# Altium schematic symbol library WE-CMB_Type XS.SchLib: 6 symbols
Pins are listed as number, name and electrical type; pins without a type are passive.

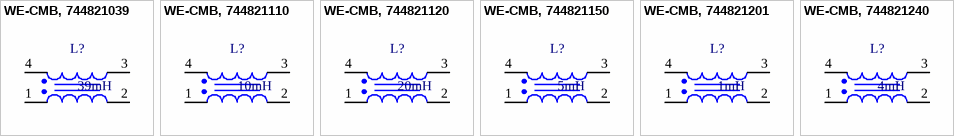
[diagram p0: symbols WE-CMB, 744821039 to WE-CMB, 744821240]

## WE-CMB, 744821039
designator L?, comment 39mH
WE-CMB Common Mode Power Line Choke, Type XS, 39mH; PartNumber: 744821039
footprint WE-CMB_Type XS
pins: 1, 2, 3, 4

## WE-CMB, 744821110
designator L?, comment 10mH
WE-CMB Common Mode Power Line Choke, Type XS, 10mH; PartNumber: 744821110
footprint WE-CMB_Type XS
pins: 1, 2, 3, 4

## WE-CMB, 744821120
designator L?, comment 20mH
WE-CMB Common Mode Power Line Choke, Type XS, 20mH; PartNumber: 744821120
footprint WE-CMB_Type XS_744821120
pins: 1, 2, 3, 4

## WE-CMB, 744821150
designator L?, comment 5mH
WE-CMB Common Mode Power Line Choke, Type XS, 5mH; PartNumber: 744821150
footprint WE-CMB_Type XS_744821150
pins: 1, 2, 3, 4

## WE-CMB, 744821201
designator L?, comment 1mH
WE-CMB Common Mode Power Line Choke, Type XS, 1mH; PartNumber: 744821201
footprint WE-CMB_Type XS
pins: 1, 2, 3, 4

## WE-CMB, 744821240
designator L?, comment 4mH
WE-CMB Common Mode Power Line Choke, Type XS, 4mH; PartNumber: 744821240
footprint WE-CMB_Type XS_744821240
pins: 1, 2, 3, 4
